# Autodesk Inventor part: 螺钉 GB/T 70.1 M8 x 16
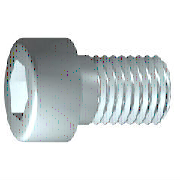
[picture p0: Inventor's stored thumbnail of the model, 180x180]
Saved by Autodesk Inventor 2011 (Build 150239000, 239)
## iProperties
Created: 2010-02
Part Number: 螺钉 GB/T 70.1 M8 x 16
Material: 低炭钢
Description: 内六角圆柱头螺钉
Document SubType Name: Modeling
Standard: GB/T 70.1-2000
Designer: Administrator
Standard Revision: 2000
Standards Organization: GB
Language: zh-CN
Size Designation: M8 x 16
Categories: <MemberInstance><Categories><Category DisplayName="紧固件" InternalName="e4da775c-781d-43d5-af7c-5136215cf5a6" Mnemonic="FSTN"><Category DisplayName="螺栓" InternalN
Density: 1 g/cm^3
IsCustomPart: 1
Author: Administrator
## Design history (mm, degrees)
body "Solid1"
sketch "Sketch1"
  geometry: L1 (-2, 0)-(16, 0); L2 (16, 0)-(16, 4); L3 (16, 4)-(1.25, 4); L4 (1.25, 4)-(0.483, 4); L5 (0.483, 4)-(0, 4); L6 (0, 4)-(0, 6.5); L7 (0, 6.5)-(-8, 6.5); L8 (-8, 6.5)-(-8, 3.464); L9 (-8, 3.464)-(-4, 3.464); L10 (-4, 3.464)-(-2, 0); L11 (-12.8, 0)-(20.8, 0) reference; L12 (0, -1.3)-(0, 7.8) reference; L13 (1.25, 4)-(0, 4)
  constraints: 22 end point, 6 parallel, 2 collinear, 2 perpendicular, 1 horizontal, 1 point on line
  dimensions: "d1" = 14.75 distance from line of L3.end L2 (= GEL); "d2" = 0.76691 distance of L4.end L3.end (computed from GAL); "d3" = 8 distance between parallel lines of L8 L6 (= KOH); "d4" = 4 distance of L8.end L9.end (= INTI); "d5" = 60 deg angle of L10 L1; "d6" = 8 diameter of L3 L1 (= GD); "d7" = 8 diameter of L5 L1 (= BDM); "d8" = 6.9282 diameter of L9 L1 (= 1.1547 x SW); "d9" = 13 diameter of L7 L1 (= KOD); "d26" = 16 distance between parallel lines of L12 L2 (= NLG)
fillet "Fillet1" dims "d17" = 0.8 (= RR)
workplane "Work Plane1"
fillet "Fillet2" dims "d30" = 0.4 (= R)
revolve "Body" stored, may be unused: angle "d10" = 90 deg
sketch "Sketch2"
  geometry: L1 (0, -9.1)-(0, 9.1) reference; L2 (-9.1, 0)-(9.1, 0) reference; L3 (3.464, 0)-(1.732, -3); L4 (1.732, -3)-(-1.732, -3); L5 (-1.732, -3)-(-3.464, 0); L6 (-3.464, 0)-(-1.732, 3); L7 (-1.732, 3)-(1.732, 3); L8 (1.732, 3)-(3.464, 0); 2 further points
  constraints: 12 end point, 1 coincident, 1 horizontal alignment, 1 point on line, 12 other
extrude "Slot" join sketch "Sketch2" stored distance "d11" = 10; taper "d12" = 0 deg
feature "Thread" dims "d13" = 14.75 (= GEL), "d14" = 0
chamfer "Chamfer1" distance "d15" = 0.76681 (= -0.5 x SPD + 0.5 x GD); stored, may be unused: second distance "d16" = 0.76681 (= GUL), angle "d27" = 45 deg
other parameters: "GD" = 8 (= NND) [user parameter; used in 2 equation terms], "NLG" = 16 [user parameter; used in 1 equation term], "GEL" = 14.75 [user parameter; used in 2 equation terms], "KOD" = 13 [user parameter; used in 1 equation term], "KOH" = 8 (= NND) [user parameter; used in 1 equation term], "INTI" = 4 [user parameter; used in 1 equation term], "GAL" = 0.76681 (= 0.61345 x PTC) [user parameter; used in 1 equation term], "GUL" = 0.76681 (= 0.61345 x PTC) [user parameter; used in 1 equation term], "BDM" = 8 (= NND) [user parameter; used in 1 equation term], "SW" = 6 [user parameter; used in 2 equation terms], "RR" = 0.8 [user parameter; used in 1 equation term], "SPD" = 6.46637 (= NND - 1.2269 x PTC) [user parameter; used in 1 equation term], "d19" = 0, "d28" = 0, "d29" = 0, "R" = 0.4 [user parameter; used in 1 equation term], "TOA" = 30 deg [user parameter], "GD1" = 6.46637 (= THREADDIA - 1.2269 x PTC) [user parameter], "THREADDIA" = 8 [user parameter; used in 1 equation term], "FAWI" = 45 deg [user parameter], "TPU" = 8 (computed from PTC) [user parameter], "PTC" = 1.25 [user parameter; used in 5 equation terms], "NND" = 8 [user parameter; used in 4 equation terms], "E0" = 6.93 (= 1.155 x SW) [user parameter]
